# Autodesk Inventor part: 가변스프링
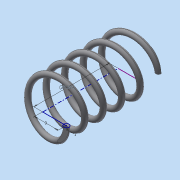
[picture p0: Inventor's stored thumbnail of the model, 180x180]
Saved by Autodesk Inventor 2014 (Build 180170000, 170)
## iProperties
Created: 2024-02
Part Number: 가변스프링
Material: 스테인레스 스틸
Document SubType Name: Modeling
Designer: dg
Density: 8.08 g/cm^3
Appearance: 반연마
Mass: 7.07035 g
Surface Area: 17.7554 cm^2
Volume: 0.875043 cm^3
Author: dg
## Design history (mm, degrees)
sketch "스케치1"
  geometry: L1 (0, 0)-(9, 0); L2 (0, 0)-(0, 28.5); L3 (0, 28.5)-(9, 28.5); C1 r 1 at (9, 0)
  constraints: 6 end point, 2 perpendicular, 1 centre point, 1 coincident, 1 horizontal, 1 parallel
  dimensions: "d0" = 28.5 distance of L1.start L2.end (derived); "d1" = 9 distance of L1.start L1.end; "d2" = 1 radius of C1
feature "코일1" sketch "스케치1" pitch "d3" = 10; turns "d5" = 5; dims "d4" = 28.5 (= d0), "d6" = 0, angle "d7" = 90 deg, angle "d8" = 90 deg, "d9" = 0, "d10" = 0
feature "분할1"
node "작업 평면1"
feature "분할2"
node "솔리드1"
other parameters: "d11" = 0
